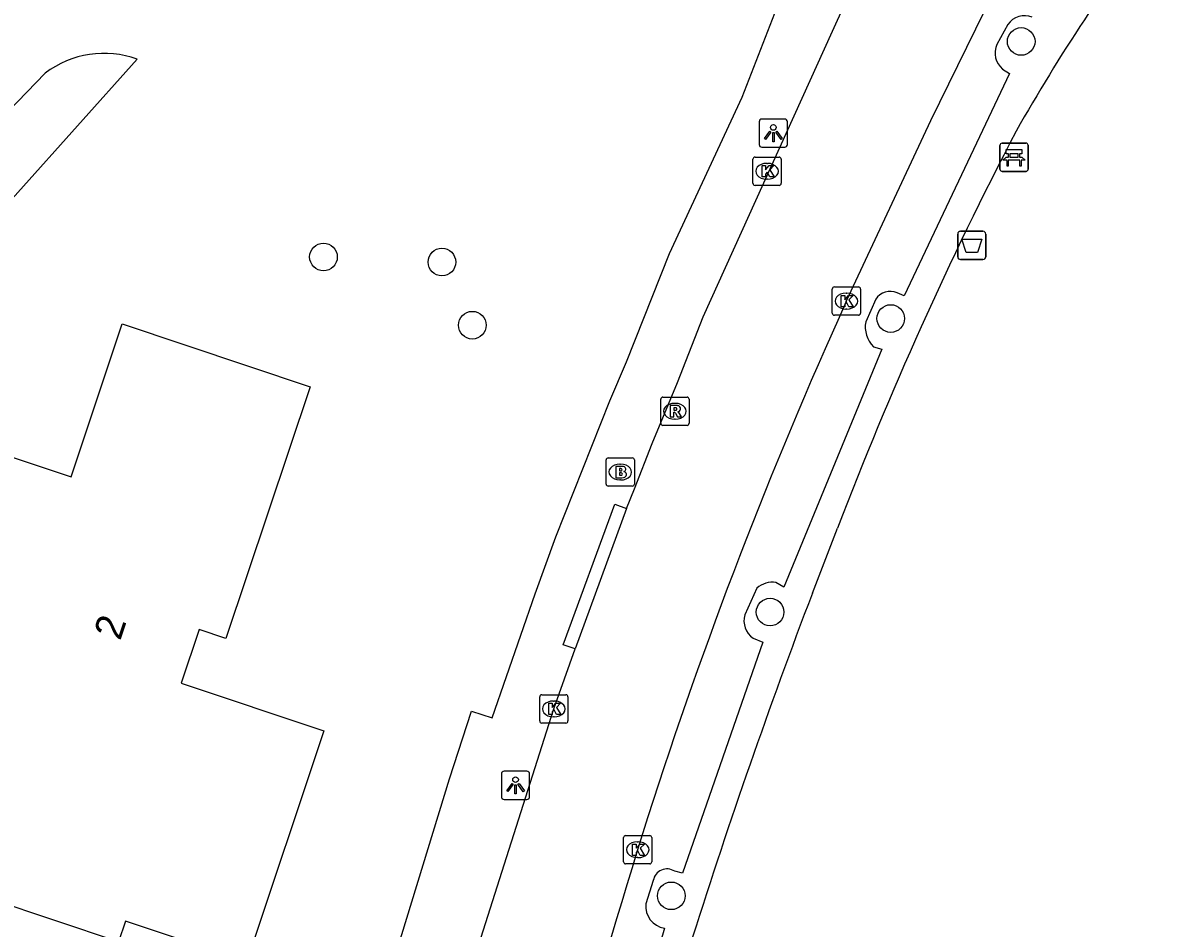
# Model space of a CAD drawing. Extents: x 161696 to 162377, y 380761 to 381673.
# Drawn here: x 161894.44 to 161934.68, y 380930.23 to 380962.24 of the extents above; entities that cross this region are included whole.
import ezdxf

# ---------------------------------------------------------------- set-up
doc = ezdxf.new("R2010")
doc.units = 0
for name, color, linetype in [('IMGEO_Afvalbak', 7, 'Continuous'), ('IMGEO_Bank', 7, 'Continuous'), ('IMGEO_Boom', 7, 'Continuous'), ('IMGEO_Brandkraan', 7, 'Continuous'), ('IMGEO_Kolk', 7, 'Continuous'), ('IMGEO_Lichtpunt', 7, 'Continuous'), ('IMGEO_Meer_plas_ven_vijver', 7, 'Continuous'), ('IMGEO_Pand', 7, 'Continuous'), ('IMGEO_Pand_nummerreeks', 7, 'Continuous'), ('IMGEO_Rijbaan_lokaal_open', 7, 'Continuous'), ('IMGEO_Rioolput', 7, 'Continuous'), ('IMGEO_Voetpad_open', 7, 'Continuous')]:
    doc.layers.add(name, color=color, linetype=linetype)

msp = doc.modelspace()

# ---------------------------------------------------------------- linework, layer by layer
at = {"layer": 'IMGEO_Afvalbak'}
for p, q in [((161927.618, 380954.872), (161928.408, 380954.872)), ((161928.408, 380954.872), (161927.618, 380954.872)), ((161927.518, 380953.972), (161927.518, 380954.772)), ((161927.518, 380954.772), (161927.518, 380953.972)), ((161928.508, 380954.772), (161928.508, 380953.972)), ((161928.508, 380953.972), (161928.508, 380954.772)), ((161928.408, 380953.872), (161927.618, 380953.872)), ((161927.618, 380953.872), (161928.408, 380953.872))]:
    msp.add_line(p, q, dxfattribs=at)
msp.add_lwpolyline([(161927.661, 380954.586), (161928.365, 380954.586), (161928.216, 380954.116), (161927.81, 380954.116), (161927.661, 380954.586)], dxfattribs=at)
for centre, start, end in [((161927.618, 380954.772), 90, 180), ((161927.618, 380954.772), 90, 180), ((161928.408, 380954.772), 0, 90), ((161928.408, 380954.772), 360, 90), ((161927.618, 380953.972), 180, 270), ((161927.618, 380953.972), 180, 270), ((161928.408, 380953.972), 270, 0), ((161928.408, 380953.972), 270, 0)]:
    msp.add_arc(centre, 0.1, start, end, dxfattribs=at)
at = {"layer": 'IMGEO_Bank'}
for p, q in [((161929.01, 380957.063), (161929.01, 380957.904)), ((161929.01, 380957.904), (161929.01, 380957.063)), ((161929.085, 380957.988), (161929.926, 380957.988)), ((161929.926, 380957.988), (161929.085, 380957.988)), ((161930.01, 380957.913), (161930.01, 380957.072)), ((161930.01, 380957.072), (161930.01, 380957.913)), ((161929.707, 380957.386), (161929.314, 380957.386)), ((161929.319, 380957.494), (161929.319, 380957.6)), ((161929.363, 380957.6), (161929.363, 380957.494)), ((161929.651, 380957.606), (161929.369, 380957.606)), ((161929.369, 380957.488), (161929.651, 380957.488)), ((161929.657, 380957.494), (161929.657, 380957.6)), ((161929.701, 380957.6), (161929.701, 380957.494)), ((161929.935, 380956.988), (161929.094, 380956.988)), ((161929.094, 380956.988), (161929.935, 380956.988))]:
    msp.add_line(p, q, dxfattribs=at)
for points in [[(161929.313, 380957.606), (161929.227, 380957.606), (161929.227, 380957.767), (161929.79, 380957.767), (161929.79, 380957.606), (161929.707, 380957.606)], [(161929.257, 380957.386), (161929.115, 380957.386), (161929.227, 380957.488), (161929.313, 380957.488)], [(161929.307, 380957.379), (161929.307, 380957.172), (161929.264, 380957.172), (161929.264, 380957.379)], [(161929.707, 380957.488), (161929.79, 380957.488), (161929.902, 380957.386), (161929.763, 380957.386)], [(161929.757, 380957.379), (161929.757, 380957.172), (161929.713, 380957.172), (161929.713, 380957.379)]]:
    msp.add_lwpolyline(points, dxfattribs=at)
for centre, radius, start, end in [((161929.088, 380957.91), 0.0779, 92.4484, 184.2845), ((161929.088, 380957.91), 0.0779, 92.4484, 184.2845), ((161929.932, 380957.91), 0.0779, 2.4484, 94.2845), ((161929.932, 380957.91), 0.0779, 2.4484, 94.2845), ((161929.257, 380957.379), 0.00671, 2.8957, 87.1043), ((161929.314, 380957.379), 0.00671, 92.8957, 177.1043), ((161929.312, 380957.599), 0.00671, 2.8957, 87.1043), ((161929.312, 380957.495), 0.00671, 272.8957, 357.1043), ((161929.369, 380957.599), 0.00671, 92.8957, 177.1043), ((161929.369, 380957.495), 0.00671, 182.8957, 267.1043), ((161929.651, 380957.599), 0.00671, 2.8957, 87.1043), ((161929.651, 380957.495), 0.00671, 272.8957, 357.1043), ((161929.708, 380957.599), 0.00671, 92.8957, 177.1043), ((161929.708, 380957.495), 0.00671, 182.8957, 267.1043), ((161929.706, 380957.379), 0.00671, 2.8957, 87.1043), ((161929.763, 380957.379), 0.00671, 92.8957, 177.1043), ((161929.088, 380957.066), 0.0779, 182.4484, 274.2845), ((161929.088, 380957.066), 0.0779, 182.4484, 274.2845), ((161929.932, 380957.066), 0.0779, 272.4484, 4.2845), ((161929.932, 380957.066), 0.0779, 272.4484, 4.2845)]:
    msp.add_arc(centre, radius, start, end, dxfattribs=at)
at = {"layer": 'IMGEO_Boom'}
for centre in [(161929.762, 380961.582), (161905.082, 380953.963), (161909.272, 380953.782), (161910.348, 380951.55), (161925.148, 380951.785), (161920.881, 380941.405), (161917.385, 380931.372)]:
    msp.add_circle(centre, 0.489, dxfattribs=at)
at = {"layer": 'IMGEO_Brandkraan'}
for p, q in [((161915.154, 380946.858), (161916.006, 380946.858)), ((161915.079, 380945.932), (161915.079, 380946.784)), ((161915.567, 380946.638), (161915.592, 380946.638)), ((161916.08, 380946.784), (161916.08, 380945.932)), ((161915.59, 380946.078), (161915.565, 380946.078)), ((161916.006, 380945.858), (161915.154, 380945.858))]:
    msp.add_line(p, q, dxfattribs=at)
for points in [[(161915.154, 380946.858), (161916.006, 380946.858)], [(161915.079, 380945.932), (161915.079, 380946.784)], [(161915.427, 380946.558), (161915.427, 380946.158), (161915.64, 380946.158)], [(161915.658, 380946.558), (161915.427, 380946.558)], [(161915.606, 380946.477), (161915.552, 380946.477), (161915.552, 380946.401)], [(161916.08, 380946.784), (161916.08, 380945.932)], [(161915.552, 380946.401), (161915.605, 380946.401)], [(161915.614, 380946.325), (161915.552, 380946.325), (161915.552, 380946.244)], [(161915.552, 380946.244), (161915.614, 380946.244)], [(161916.006, 380945.858), (161915.154, 380945.858)]]:
    msp.add_lwpolyline(points, dxfattribs=at)
for centre, radius, start, end in [((161915.156, 380946.782), 0.0765, 91.552, 178.448), ((161915.156, 380946.782), 0.0765, 91.552, 178.448), ((161916.004, 380946.782), 0.0765, 1.552, 88.448), ((161916.004, 380946.782), 0.0765, 1.552, 88.448), ((161915.607, 380946.439), 0.0379, 267.8285, 90.9355), ((161915.662, 380946.413), 0.145, 59.4692, 91.5367), ((161915.687, 380946.46), 0.0922, 285.5137, 58.1501), ((161915.615, 380946.284), 0.0404, 269.8759, 90.5077), ((161915.646, 380946.409), 0.251, 268.6676, 293.5347), ((161915.692, 380946.268), 0.105, 301.3115, 78.989), ((161915.156, 380945.934), 0.0765, 181.552, 268.448), ((161915.156, 380945.934), 0.0765, 181.552, 268.448), ((161916.004, 380945.934), 0.0765, 271.552, 358.448), ((161916.004, 380945.934), 0.0765, 271.552, 358.448)]:
    msp.add_arc(centre, radius, start, end, dxfattribs=at)
for centre, major_axis, ratio, start_param, end_param in [((161915.566, 380946.358), (-0.387, 0.002), 0.722429, 4.712389, 7.853982), ((161915.591, 380946.358), (-0.39, 0.002), 0.717154, 1.570796, 4.712389)]:
    msp.add_ellipse(centre, major_axis=major_axis, ratio=ratio, start_param=start_param, end_param=end_param, dxfattribs=at)
at = {"layer": 'IMGEO_Kolk'}
for p, q in [((161920.274, 380956.567), (161920.274, 380957.419)), ((161920.349, 380957.493), (161921.201, 380957.493)), ((161920.762, 380957.273), (161920.787, 380957.273)), ((161921.275, 380957.419), (161921.275, 380956.567)), ((161921.201, 380956.493), (161920.349, 380956.493)), ((161920.785, 380956.713), (161920.76, 380956.713)), ((161923.153, 380952.902), (161924.005, 380952.902)), ((161923.078, 380951.976), (161923.078, 380952.828)), ((161923.566, 380952.682), (161923.591, 380952.682)), ((161924.079, 380952.828), (161924.079, 380951.976)), ((161923.589, 380952.122), (161923.564, 380952.122)), ((161924.005, 380951.902), (161923.153, 380951.902)), ((161912.73, 380937.555), (161912.73, 380938.407)), ((161912.805, 380938.481), (161913.657, 380938.481)), ((161913.731, 380938.407), (161913.731, 380937.555)), ((161913.218, 380938.261), (161913.243, 380938.261)), ((161913.241, 380937.701), (161913.216, 380937.701)), ((161913.657, 380937.481), (161912.805, 380937.481)), ((161915.696, 380932.577), (161915.696, 380933.429)), ((161915.771, 380933.503), (161916.623, 380933.503)), ((161916.184, 380933.283), (161916.209, 380933.283)), ((161916.697, 380933.429), (161916.697, 380932.577)), ((161916.207, 380932.723), (161916.182, 380932.723)), ((161916.623, 380932.503), (161915.771, 380932.503))]:
    msp.add_line(p, q, dxfattribs=at)
for points in [[(161920.274, 380956.567), (161920.274, 380957.419)], [(161920.349, 380957.493), (161921.201, 380957.493)], [(161921.275, 380957.419), (161921.275, 380956.567)], [(161920.595, 380957.193), (161920.718, 380957.193), (161920.718, 380957.042), (161920.848, 380957.193), (161921.012, 380957.193), (161920.866, 380957.042), (161921.019, 380956.793), (161920.867, 380956.793), (161920.782, 380956.957), (161920.718, 380956.89), (161920.718, 380956.793), (161920.595, 380956.793), (161920.595, 380957.193)], [(161921.201, 380956.493), (161920.349, 380956.493)], [(161923.153, 380952.902), (161924.005, 380952.902)], [(161923.078, 380951.976), (161923.078, 380952.828)], [(161923.399, 380952.602), (161923.522, 380952.602), (161923.522, 380952.451), (161923.652, 380952.602), (161923.816, 380952.602), (161923.67, 380952.451), (161923.823, 380952.202), (161923.671, 380952.202), (161923.586, 380952.366), (161923.522, 380952.299), (161923.522, 380952.202), (161923.399, 380952.202), (161923.399, 380952.602)], [(161924.079, 380952.828), (161924.079, 380951.976)], [(161924.005, 380951.902), (161923.153, 380951.902)], [(161912.73, 380937.555), (161912.73, 380938.407)], [(161912.805, 380938.481), (161913.657, 380938.481)], [(161913.731, 380938.407), (161913.731, 380937.555)], [(161913.051, 380938.181), (161913.174, 380938.181), (161913.174, 380938.03), (161913.304, 380938.181), (161913.468, 380938.181), (161913.322, 380938.03), (161913.475, 380937.781), (161913.323, 380937.781), (161913.238, 380937.945), (161913.174, 380937.878), (161913.174, 380937.781), (161913.051, 380937.781), (161913.051, 380938.181)], [(161913.657, 380937.481), (161912.805, 380937.481)], [(161915.696, 380932.577), (161915.696, 380933.429)], [(161915.771, 380933.503), (161916.623, 380933.503)], [(161916.017, 380933.203), (161916.14, 380933.203), (161916.14, 380933.052), (161916.27, 380933.203), (161916.434, 380933.203), (161916.288, 380933.052), (161916.441, 380932.803), (161916.289, 380932.803), (161916.204, 380932.967), (161916.14, 380932.9), (161916.14, 380932.803), (161916.017, 380932.803), (161916.017, 380933.203)], [(161916.697, 380933.429), (161916.697, 380932.577)], [(161916.623, 380932.503), (161915.771, 380932.503)]]:
    msp.add_lwpolyline(points, dxfattribs=at)
for centre, start, end in [((161920.351, 380957.417), 91.552, 178.448), ((161920.351, 380957.417), 91.552, 178.448), ((161921.199, 380957.417), 1.552, 88.448), ((161921.199, 380957.417), 1.552, 88.448), ((161920.351, 380956.569), 181.552, 268.448), ((161920.351, 380956.569), 181.552, 268.448), ((161921.199, 380956.569), 271.552, 358.448), ((161921.199, 380956.569), 271.552, 358.448), ((161923.155, 380952.826), 91.552, 178.448), ((161923.155, 380952.826), 91.552, 178.448), ((161924.003, 380952.826), 1.552, 88.448), ((161924.003, 380952.826), 1.552, 88.448), ((161923.155, 380951.978), 181.552, 268.448), ((161923.155, 380951.978), 181.552, 268.448), ((161924.003, 380951.978), 271.552, 358.448), ((161924.003, 380951.978), 271.552, 358.448), ((161912.807, 380938.405), 91.552, 178.448), ((161912.807, 380938.405), 91.552, 178.448), ((161913.655, 380938.405), 1.552, 88.448), ((161913.655, 380938.405), 1.552, 88.448), ((161912.807, 380937.557), 181.552, 268.448), ((161912.807, 380937.557), 181.552, 268.448), ((161913.655, 380937.557), 271.552, 358.448), ((161913.655, 380937.557), 271.552, 358.448), ((161915.773, 380933.427), 91.552, 178.448), ((161915.773, 380933.427), 91.552, 178.448), ((161916.621, 380933.427), 1.552, 88.448), ((161916.621, 380933.427), 1.552, 88.448), ((161915.773, 380932.579), 181.552, 268.448), ((161915.773, 380932.579), 181.552, 268.448), ((161916.621, 380932.579), 271.552, 358.448), ((161916.621, 380932.579), 271.552, 358.448)]:
    msp.add_arc(centre, 0.0765, start, end, dxfattribs=at)
for centre, major_axis, ratio, start_param, end_param in [((161920.761, 380956.993), (-0.387, 0.002), 0.722429, 4.712389, 7.853982), ((161920.786, 380956.993), (-0.39, 0.002), 0.717154, 1.570796, 4.712389), ((161923.565, 380952.402), (-0.387, 0.002), 0.722429, 4.712389, 7.853982), ((161923.59, 380952.402), (-0.39, 0.002), 0.717154, 1.570796, 4.712389), ((161913.217, 380937.981), (-0.387, 0.002), 0.722429, 4.712389, 7.853982), ((161913.242, 380937.981), (-0.39, 0.002), 0.717154, 1.570796, 4.712389), ((161916.183, 380933.003), (-0.387, 0.002), 0.722429, 4.712389, 7.853982), ((161916.208, 380933.003), (-0.39, 0.002), 0.717154, 1.570796, 4.712389)]:
    msp.add_ellipse(centre, major_axis=major_axis, ratio=ratio, start_param=start_param, end_param=end_param, dxfattribs=at)
at = {"layer": 'IMGEO_Lichtpunt'}
for p, q in [((161920.496, 380958.745), (161920.496, 380957.938)), ((161920.496, 380958.745), (161920.496, 380957.938)), ((161921.398, 380958.84), (161920.59, 380958.84)), ((161921.398, 380958.84), (161920.59, 380958.84)), ((161921.492, 380957.938), (161921.492, 380958.745)), ((161921.492, 380957.938), (161921.492, 380958.745)), ((161920.59, 380957.844), (161921.398, 380957.844)), ((161920.59, 380957.844), (161921.398, 380957.844)), ((161911.377, 380935.682), (161911.377, 380934.875)), ((161911.377, 380935.682), (161911.377, 380934.875)), ((161912.279, 380935.777), (161911.471, 380935.777)), ((161912.279, 380935.777), (161911.471, 380935.777)), ((161912.373, 380934.875), (161912.373, 380935.682)), ((161912.373, 380934.875), (161912.373, 380935.682)), ((161911.471, 380934.781), (161912.279, 380934.781)), ((161911.471, 380934.781), (161912.279, 380934.781))]:
    msp.add_line(p, q, dxfattribs=at)
for points in [[(161920.87, 380958.409), (161920.909, 380958.381), (161920.721, 380958.119), (161920.683, 380958.146), (161920.87, 380958.409)], [(161920.972, 380958.361), (161921.019, 380958.361), (161921.019, 380958.039), (161920.972, 380958.039), (161920.972, 380958.361)], [(161921.082, 380958.381), (161921.12, 380958.408), (161921.307, 380958.146), (161921.268, 380958.118), (161921.082, 380958.381)], [(161911.751, 380935.346), (161911.79, 380935.318), (161911.602, 380935.056), (161911.564, 380935.083), (161911.751, 380935.346)], [(161911.853, 380935.298), (161911.9, 380935.298), (161911.9, 380934.976), (161911.853, 380934.976), (161911.853, 380935.298)], [(161911.963, 380935.318), (161912.001, 380935.345), (161912.188, 380935.083), (161912.149, 380935.055), (161911.963, 380935.318)]]:
    msp.add_lwpolyline(points, dxfattribs=at)
for centre in [(161920.995, 380958.543), (161911.876, 380935.48)]:
    msp.add_circle(centre, 0.0994, dxfattribs=at)
for centre, start, end in [((161920.59, 380958.745), 90, 180), ((161920.59, 380958.745), 90, 180), ((161921.398, 380958.745), 0, 90), ((161921.398, 380958.745), 0, 90), ((161920.59, 380957.938), 180, 270), ((161920.59, 380957.938), 180, 270), ((161921.398, 380957.938), 270, 0), ((161921.398, 380957.938), 270, 360), ((161911.471, 380935.682), 90, 180), ((161911.471, 380935.682), 90, 180), ((161912.279, 380935.682), 0, 90), ((161912.279, 380935.682), 0, 90), ((161911.471, 380934.875), 180, 270), ((161911.471, 380934.875), 180, 270), ((161912.279, 380934.875), 270, 0), ((161912.279, 380934.875), 270, 360)]:
    msp.add_arc(centre, 0.0946, start, end, dxfattribs=at)
at = {"layer": 'IMGEO_Meer_plas_ven_vijver'}
for points in [[(161898.49, 380960.955), (161892.147, 380953.884), (161882.378, 380942.741), (161865.694, 380925.863)], [(161891.512, 380956.258), (161893.282, 380958.444), (161895.242, 380960.46)]]:
    msp.add_lwpolyline(points, dxfattribs=at)
msp.add_arc((161897.318, 380957.741), 3.421, 69.966, 127.3646, dxfattribs=at)
at = {"layer": 'IMGEO_Pand'}
msp.add_lwpolyline([(161904.606, 380949.376), (161901.633, 380940.472), (161900.683, 380940.788), (161900.051, 380938.888), (161905.097, 380937.205), (161902.371, 380929.046), (161898.075, 380930.482), (161897.828, 380929.743), (161893.314, 380931.252), (161893.562, 380931.992), (161889.275, 380933.425), (161889.424, 380933.871), (161891.494, 380940.065), (161887.672, 380941.343), (161887.466, 380940.984), (161887.136, 380941.173), (161890.851, 380947.961), (161896.162, 380946.187), (161897.967, 380951.593), (161904.606, 380949.376)], dxfattribs=at)
at = {"layer": 'IMGEO_Rijbaan_lokaal_open'}
for points in [[(161915.806, 380945.07), (161916.081, 380945.769), (161916.709, 380947.369), (161917.602, 380949.522), (161918.511, 380951.841), (161923.089, 380961.942), (161924.606, 380965.289), (161925.681, 380967.252), (161927.496, 380970.047)], [(161923.57, 380952.384), (161926.561, 380958.791), (161928.479, 380962.675)], [(161915.806, 380945.07), (161913.986, 380940.104)], [(161909.204, 380924.931), (161910.235, 380928.573), (161913.231, 380937.981), (161913.986, 380940.104)]]:
    msp.add_lwpolyline(points, dxfattribs=at)
for centre, radius, start, end in [((162078.053, 380882.469), 169.567, 155.64955, 162.25057), ((162183.467, 380850.295), 279.775, 162.55658, 166.67153)]:
    msp.add_arc(centre, radius, start, end, dxfattribs=at)
at = {"layer": 'IMGEO_Rioolput'}
for p, q in [((161917.014, 380948.081), (161917.014, 380948.933)), ((161917.089, 380949.007), (161917.941, 380949.007)), ((161918.015, 380948.933), (161918.015, 380948.081)), ((161917.502, 380948.787), (161917.527, 380948.787)), ((161917.525, 380948.227), (161917.5, 380948.227)), ((161917.941, 380948.007), (161917.089, 380948.007))]:
    msp.add_line(p, q, dxfattribs=at)
for points in [[(161917.014, 380948.081), (161917.014, 380948.933)], [(161917.089, 380949.007), (161917.941, 380949.007)], [(161918.015, 380948.933), (161918.015, 380948.081)], [(161917.603, 380948.705), (161917.351, 380948.707), (161917.351, 380948.307)], [(161917.351, 380948.307), (161917.475, 380948.307), (161917.475, 380948.469), (161917.486, 380948.469)], [(161917.529, 380948.626), (161917.475, 380948.626), (161917.475, 380948.545)], [(161917.475, 380948.545), (161917.527, 380948.545)], [(161917.533, 380948.44), (161917.604, 380948.307), (161917.744, 380948.307), (161917.679, 380948.433)], [(161917.941, 380948.007), (161917.089, 380948.007)]]:
    msp.add_lwpolyline(points, dxfattribs=at)
for centre, radius, start, end in [((161917.091, 380948.931), 0.0765, 91.552, 178.448), ((161917.091, 380948.931), 0.0765, 91.552, 178.448), ((161917.939, 380948.931), 0.0765, 1.552, 88.448), ((161917.939, 380948.931), 0.0765, 1.552, 88.448), ((161917.485, 380948.416), 0.0533, 26.0293, 88.6989), ((161917.511, 380948.734), 0.19, 274.7715, 282.9687), ((161917.535, 380948.53), 0.0964, 77.0061, 93.1865), ((161917.549, 380948.587), 0.0378, 276.6634, 79.6772), ((161917.602, 380948.595), 0.109, 350.3612, 89.416), ((161917.6, 380948.595), 0.112, 277.5842, 350.9817), ((161917.584, 380948.38), 0.108, 29.5134, 73.7905), ((161917.091, 380948.083), 0.0765, 181.552, 268.448), ((161917.091, 380948.083), 0.0765, 181.552, 268.448), ((161917.939, 380948.083), 0.0765, 271.552, 358.448), ((161917.939, 380948.083), 0.0765, 271.552, 358.448)]:
    msp.add_arc(centre, radius, start, end, dxfattribs=at)
for centre, major_axis, ratio, start_param, end_param in [((161917.501, 380948.507), (-0.387, 0.002), 0.722429, 4.712389, 7.853982), ((161917.526, 380948.507), (-0.39, 0.002), 0.717154, 1.570796, 4.712389)]:
    msp.add_ellipse(centre, major_axis=major_axis, ratio=ratio, start_param=start_param, end_param=end_param, dxfattribs=at)
at = {"layer": 'IMGEO_Voetpad_open'}
for points in [[(161891.703, 380835.311), (161897.898, 380881.646), (161899.607, 380894.429), (161899.669, 380894.921), (161903.243, 380915.524), (161904.111, 380919.431), (161905.911, 380926.612), (161907.276, 380928.114), (161909.538, 380935.504), (161910.322, 380937.903), (161911.048, 380937.662), (161912.574, 380942.048), (161913.306, 380944.069), (161915.212, 380948.879), (161915.8, 380950.259), (161917.318, 380954.087), (161919.894, 380959.612), (161922.862, 380967.263)], [(161929.29, 380962.18), (161928.898, 380961.48)], [(161929.103, 380960.605), (161929.345, 380960.453), (161925.62, 380952.583), (161925.378, 380952.697)], [(161924.617, 380952.466), (161924.264, 380951.666)], [(161924.533, 380950.79), (161924.838, 380950.702), (161921.368, 380942.287), (161921.088, 380942.451)], [(161913.986, 380940.104), (161913.558, 380940.248), (161915.388, 380945.223), (161915.806, 380945.07)], [(161922.375, 380942.071), (161923.268, 380944.378)], [(161920.416, 380942.247), (161919.987, 380941.306)], [(161920.281, 380940.481), (161920.624, 380940.342), (161917.776, 380932.17), (161917.507, 380932.239)], [(161916.748, 380931.914), (161916.484, 380931.088)], [(161917.146, 380930.226), (161914.528, 380921.191), (161914.325, 380921.254)]]:
    msp.add_lwpolyline(points, dxfattribs=at)
for centre, radius, start, end in [((161986.989, 380925.932), 65.957, 142.47282, 150.49493), ((161929.875, 380961.79), 0.703, 66.7663, 146.3148), ((161929.601, 380961.183), 0.763, 157.0974, 229.2741), ((162047.034, 380897.116), 132.483, 152.43851, 159.09989), ((161925.135, 380952.127), 0.619, 66.923, 146.8481), ((161925.237, 380951.486), 0.99, 169.4918, 224.6493), ((161920.96, 380941.665), 0.796, 80.7192, 133.0544), ((162131.741, 380862.326), 224.038, 159.14873, 162.44172), ((161920.702, 380941.096), 0.746, 163.6417, 235.5868), ((161917.233, 380931.831), 0.492, 56.0693, 170.2914), ((161917.265, 380931.003), 0.786, 173.7679, 261.2793)]:
    msp.add_arc(centre, radius, start, end, dxfattribs=at)

# ---------------------------------------------------------------- texts
at = {"layer": 'IMGEO_Pand_nummerreeks'}
msp.add_text('2', height=1, rotation=71.582, dxfattribs=at).set_placement((161897.889, 380940.371))

doc.saveas('drawing.dxf')
